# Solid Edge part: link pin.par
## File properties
Author: Robert a Rhodes jr
Template: Normal.par
Last saved by: CADCIM
Revision: 7
Application: Solid Edge
Accuracy: 0.99
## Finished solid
Body 1: solid body, 5 faces, 4 edges, 0 vertices.
  Faces by surface: plane 3, cylinder 2
  Edges by curve: circle 4
Bounding box of the edges (mm): 15.000 x 15.000 x 50.000, from (-7.5, -7.5, -22.7536) to (7.5, 7.5, 27.2464).
Cylindrical faces by radius (mm): R5 x1, R7.5 x1
Planar faces by outward normal: +z 1, -z 2
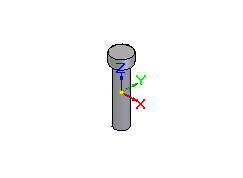
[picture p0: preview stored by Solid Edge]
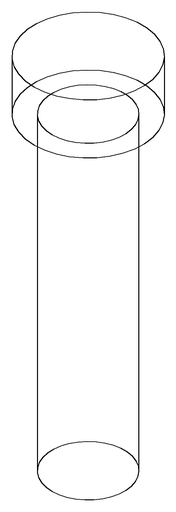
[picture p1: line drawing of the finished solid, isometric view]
